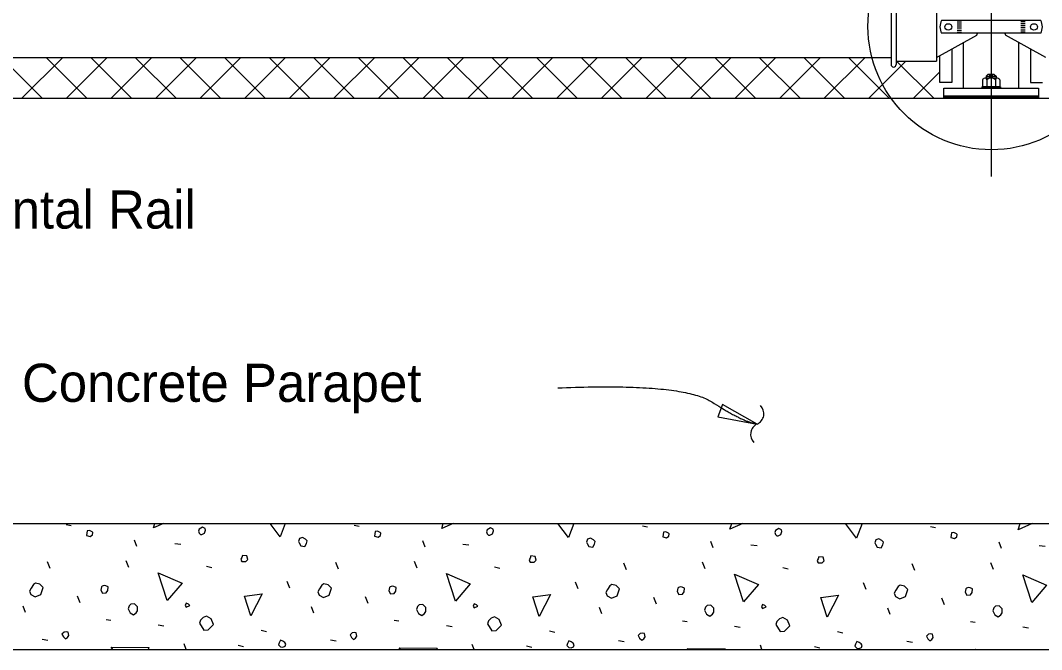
# Model space of a CAD drawing. Extents: x 110698 to 110915, y 110390 to 110472.
# Drawn here: x 110781.01 to 110786.41, y 110452.9 to 110456.22 of the extents above; entities that cross this region are included whole.
import ezdxf

# ---------------------------------------------------------------- set-up
doc = ezdxf.new("R2010")
doc.units = 0
for name, color, linetype in [('AdhocPoint_dp', 7, 'Continuous'), ('Border', 7, 'Continuous'), ('PlotBorder_dp', 7, 'Continuous'), ('SheetBorder_dp', 7, 'Continuous'), ('SheetLines_dp', 7, 'Continuous'), ('TextMisc', 7, 'Continuous')]:
    doc.layers.add(name, color=color, linetype=linetype)

msp = doc.modelspace()

# ---------------------------------------------------------------- linework, layer by layer
at = {"layer": 'AdhocPoint_dp'}
msp.add_line((110786.1408, 110463.3097), (110786.1408, 110455.3996), dxfattribs=at)
at = {"layer": 'PlotBorder_dp'}
msp.add_line((110786.1408, 110455.8731), (110786.1408, 110455.8724), dxfattribs=at)
msp.add_lwpolyline([(110784.9036, 110454.0892), (110784.72, 110454.1937), (110784.6958, 110454.1274)], close=True, dxfattribs=at)
msp.add_circle((110786.1422, 110456.193), 0.6527, dxfattribs=at)
for centre, start, end in [((110784.8793, 110454.1441), 294.1466, 45.8738), ((110784.9281, 110454.0353), 114.1466, 225.8738)]:
    msp.add_arc(centre, 0.0596, start, end, dxfattribs=at)
msp.add_open_spline([(110783.8491, 110454.2807), (110784.5058, 110454.309), (110784.8272, 110454.1009), (110784.9038, 110454.0897)], degree=2, dxfattribs=at)
at = {"layer": 'SheetBorder_dp'}
for p, q in [((110781.1232, 110455.8133), (110780.9097, 110456.0268)), ((110781.2293, 110456.0268), (110781.0157, 110455.8133)), ((110781.3589, 110455.8133), (110781.1454, 110456.0268)), ((110781.465, 110456.0268), (110781.2514, 110455.8133)), ((110781.5946, 110455.8133), (110781.3811, 110456.0268)), ((110781.7007, 110456.0268), (110781.4871, 110455.8133)), ((110781.8303, 110455.8133), (110781.6168, 110456.0268)), ((110781.9364, 110456.0268), (110781.7228, 110455.8133)), ((110782.066, 110455.8133), (110781.8525, 110456.0268)), ((110782.1721, 110456.0268), (110781.9586, 110455.8133)), ((110782.3017, 110455.8133), (110782.0882, 110456.0268)), ((110782.4078, 110456.0268), (110782.1943, 110455.8133)), ((110782.5374, 110455.8133), (110782.3239, 110456.0268)), ((110782.6435, 110456.0268), (110782.43, 110455.8133)), ((110782.7731, 110455.8133), (110782.5596, 110456.0268)), ((110782.8792, 110456.0268), (110782.6657, 110455.8133)), ((110783.0088, 110455.8133), (110782.7953, 110456.0268)), ((110783.1149, 110456.0268), (110782.9014, 110455.8133)), ((110783.2445, 110455.8133), (110783.031, 110456.0268)), ((110783.3506, 110456.0268), (110783.1371, 110455.8133)), ((110783.4802, 110455.8133), (110783.2667, 110456.0268)), ((110783.5863, 110456.0268), (110783.3728, 110455.8133)), ((110783.7159, 110455.8133), (110783.5024, 110456.0268)), ((110783.822, 110456.0268), (110783.6085, 110455.8133)), ((110783.9516, 110455.8133), (110783.7381, 110456.0268)), ((110784.0577, 110456.0268), (110783.8442, 110455.8133)), ((110784.1873, 110455.8133), (110783.9738, 110456.0268)), ((110784.2934, 110456.0268), (110784.0799, 110455.8133)), ((110784.423, 110455.8133), (110784.2095, 110456.0268)), ((110784.5291, 110456.0268), (110784.3156, 110455.8133)), ((110784.6587, 110455.8133), (110784.4452, 110456.0268)), ((110784.7648, 110456.0268), (110784.5513, 110455.8133)), ((110784.8944, 110455.8133), (110784.6809, 110456.0268)), ((110785.0005, 110456.0268), (110784.787, 110455.8133)), ((110785.1301, 110455.8133), (110784.9166, 110456.0268)), ((110785.2362, 110456.0268), (110785.0227, 110455.8133)), ((110785.3658, 110455.8133), (110785.1523, 110456.0268)), ((110785.4719, 110456.0268), (110785.2584, 110455.8133)), ((110785.6015, 110455.8133), (110785.388, 110456.0268)), ((110785.6904, 110456.0096), (110785.4941, 110455.8133)), ((110785.8372, 110455.8133), (110785.6409, 110456.0096)), ((110785.8699, 110455.9534), (110785.7298, 110455.8133)), ((110786.1296, 110455.9348), (110786.1503, 110455.9348)), ((110786.1296, 110455.9251), (110786.1503, 110455.9251)), ((110785.8908, 110455.8202), (110786.3908, 110455.8202)), ((110785.8908, 110455.8167), (110786.3908, 110455.8167)), ((110781.2486, 110453.5577), (110781.2751, 110453.5524)), ((110782.7724, 110453.5542), (110782.799, 110453.5489)), ((110784.2963, 110453.5507), (110784.3228, 110453.5453)), ((110785.8201, 110453.5471), (110785.8466, 110453.5418)), ((110781.6234, 110453.4411), (110781.611, 110453.4746)), ((110781.8232, 110453.457), (110781.855, 110453.4534)), ((110783.1472, 110453.4375), (110783.1348, 110453.4711)), ((110783.347, 110453.4534), (110783.3788, 110453.4499)), ((110784.671, 110453.434), (110784.6586, 110453.4676)), ((110784.8708, 110453.4499), (110784.9026, 110453.4464)), ((110786.1948, 110453.4304), (110786.1825, 110453.464)), ((110786.3946, 110453.4464), (110786.4264, 110453.4428)), ((110781.1655, 110453.3261), (110781.1514, 110453.3615)), ((110781.581, 110453.3314), (110781.5668, 110453.3668)), ((110781.9911, 110453.3385), (110782.0194, 110453.3314)), ((110782.6894, 110453.3226), (110782.6752, 110453.358)), ((110783.1048, 110453.3279), (110783.0906, 110453.3633)), ((110783.5149, 110453.335), (110783.5432, 110453.3279)), ((110784.2132, 110453.3191), (110784.199, 110453.3544)), ((110784.6286, 110453.3244), (110784.6145, 110453.3597)), ((110785.0387, 110453.3314), (110785.067, 110453.3244)), ((110785.737, 110453.3155), (110785.7228, 110453.3509)), ((110786.1524, 110453.3208), (110786.1383, 110453.3562)), ((110782.433, 110453.2218), (110782.4189, 110453.2572)), ((110783.9568, 110453.2183), (110783.9427, 110453.2537)), ((110785.4807, 110453.2148), (110785.4665, 110453.2501)), ((110781.3229, 110453.1441), (110781.3087, 110453.1794)), ((110782.8467, 110453.1405), (110782.8325, 110453.1759)), ((110784.3705, 110453.137), (110784.3564, 110453.1723)), ((110785.8943, 110453.1335), (110785.8802, 110453.1688)), ((110781.0347, 110453.0928), (110781.0224, 110453.1264)), ((110782.5585, 110453.0893), (110782.5462, 110453.1229)), ((110784.0824, 110453.0857), (110784.07, 110453.1193)), ((110785.6062, 110453.0822), (110785.5938, 110453.1158)), ((110781.4608, 110453.0557), (110781.4855, 110453.0521)), ((110782.9846, 110453.0521), (110783.0093, 110453.0486)), ((110781.7365, 110453.0274), (110781.7666, 110453.0221)), ((110782.281, 110452.9991), (110782.3093, 110452.992)), ((110783.2603, 110453.0239), (110783.2904, 110453.0186)), ((110784.5084, 110453.0486), (110784.5331, 110453.0451)), ((110784.7842, 110453.0203), (110784.8142, 110453.015)), ((110786.0322, 110453.0451), (110786.057, 110453.0415)), ((110786.308, 110453.0168), (110786.338, 110453.0115)), ((110781.1231, 110452.9514), (110781.1532, 110452.9461)), ((110782.6469, 110452.9478), (110782.677, 110452.9425)), ((110783.8048, 110452.9956), (110783.8331, 110452.9885)), ((110784.1707, 110452.9443), (110784.2008, 110452.939)), ((110785.3286, 110452.992), (110785.3569, 110452.985)), ((110781.8837, 110452.8966), (110781.8726, 110452.9266)), ((110782.159, 110452.9196), (110782.1873, 110452.9125)), ((110783.4062, 110452.8966), (110783.3965, 110452.9231)), ((110783.6828, 110452.916), (110783.7111, 110452.909)), ((110784.9287, 110452.8966), (110784.9203, 110452.9196)), ((110785.2067, 110452.9125), (110785.2349, 110452.9054)), ((110785.6946, 110452.9408), (110785.7246, 110452.9355))]:
    msp.add_line(p, q, dxfattribs=at)
msp.add_lwpolyline([(110785.8908, 110455.8237), (110786.3908, 110455.8237), (110786.3908, 110455.8133), (110785.8908, 110455.8133)], close=True, dxfattribs=at)
for points in [[(110781.7118, 110453.54), (110781.7189, 110453.5632)], [(110781.7634, 110453.5632), (110781.7118, 110453.54)], [(110781.9593, 110453.5047), (110781.9663, 110453.5047), (110781.9805, 110453.5118), (110781.9858, 110453.5277), (110781.984, 110453.5365), (110781.9699, 110453.5436), (110781.9522, 110453.533), (110781.9487, 110453.5224), (110781.9522, 110453.5118), (110781.9593, 110453.5047)], [(110782.3818, 110453.4923), (110782.3279, 110453.5632)], [(110782.4083, 110453.5632), (110782.3818, 110453.4923)], [(110783.2356, 110453.5365), (110783.2438, 110453.5632)], [(110783.2951, 110453.5632), (110783.2356, 110453.5365)], [(110783.4831, 110453.5012), (110783.4902, 110453.5012), (110783.5043, 110453.5082), (110783.5096, 110453.5241), (110783.5078, 110453.533), (110783.4937, 110453.54), (110783.476, 110453.5294), (110783.4725, 110453.5188), (110783.476, 110453.5082), (110783.4831, 110453.5012)], [(110783.9056, 110453.4888), (110783.849, 110453.5632)], [(110783.9334, 110453.5632), (110783.9056, 110453.4888)], [(110784.7594, 110453.533), (110784.7687, 110453.5632)], [(110784.8268, 110453.5632), (110784.7594, 110453.533)], [(110785.0069, 110453.4976), (110785.014, 110453.4976), (110785.0281, 110453.5047), (110785.0334, 110453.5206), (110785.0316, 110453.5294), (110785.0175, 110453.5365), (110784.9998, 110453.5259), (110784.9963, 110453.5153), (110784.9998, 110453.5047), (110785.0069, 110453.4976)], [(110785.4294, 110453.4852), (110785.3701, 110453.5632)], [(110785.4585, 110453.5632), (110785.4294, 110453.4852)], [(110786.2832, 110453.5294), (110786.2936, 110453.5632)], [(110786.3585, 110453.5632), (110786.2832, 110453.5294)], [(110781.3565, 110453.4994), (110781.3759, 110453.4941), (110781.3883, 110453.5029), (110781.39, 110453.5153), (110781.3865, 110453.5188), (110781.3724, 110453.5259), (110781.36, 110453.5241), (110781.3582, 110453.5118), (110781.3565, 110453.4994)], [(110782.4808, 110453.4605), (110782.4896, 110453.4446), (110782.5108, 110453.4411), (110782.5197, 110453.457), (110782.5232, 110453.4711), (110782.5143, 110453.4799), (110782.4984, 110453.4888), (110782.4825, 110453.4835), (110782.4772, 110453.4676), (110782.4808, 110453.4605)], [(110782.8803, 110453.4959), (110782.8997, 110453.4905), (110782.9121, 110453.4994), (110782.9139, 110453.5118), (110782.9103, 110453.5153), (110782.8962, 110453.5224), (110782.8838, 110453.5206), (110782.882, 110453.5082), (110782.8803, 110453.4959)], [(110784.0046, 110453.457), (110784.0134, 110453.4411), (110784.0346, 110453.4375), (110784.0435, 110453.4534), (110784.047, 110453.4676), (110784.0382, 110453.4764), (110784.0223, 110453.4852), (110784.0063, 110453.4799), (110784.001, 110453.464), (110784.0046, 110453.457)], [(110784.4041, 110453.4923), (110784.4235, 110453.487), (110784.4359, 110453.4959), (110784.4377, 110453.5082), (110784.4341, 110453.5118), (110784.42, 110453.5188), (110784.4076, 110453.5171), (110784.4059, 110453.5047), (110784.4041, 110453.4923)], [(110785.5284, 110453.4534), (110785.5372, 110453.4375), (110785.5584, 110453.434), (110785.5673, 110453.4499), (110785.5708, 110453.464), (110785.562, 110453.4729), (110785.5461, 110453.4817), (110785.5302, 110453.4764), (110785.5249, 110453.4605), (110785.5284, 110453.4534)], [(110785.9279, 110453.4888), (110785.9474, 110453.4835), (110785.9597, 110453.4923), (110785.9615, 110453.5047), (110785.958, 110453.5082), (110785.9438, 110453.5153), (110785.9314, 110453.5135), (110785.9297, 110453.5012), (110785.9279, 110453.4888)], [(110782.1785, 110453.3633), (110782.1997, 110453.3633), (110782.2103, 110453.3739), (110782.205, 110453.3933), (110782.182, 110453.3951), (110782.1785, 110453.3845), (110782.1732, 110453.3756), (110782.1785, 110453.3633), (110782.1749, 110453.3668)], [(110783.7023, 110453.3597), (110783.7235, 110453.3597), (110783.7341, 110453.3703), (110783.7288, 110453.3898), (110783.7058, 110453.3916), (110783.7023, 110453.3809), (110783.697, 110453.3721), (110783.7023, 110453.3597), (110783.6988, 110453.3633)], [(110785.2261, 110453.3562), (110785.2473, 110453.3562), (110785.2579, 110453.3668), (110785.2526, 110453.3862), (110785.2296, 110453.388), (110785.2261, 110453.3774), (110785.2208, 110453.3686), (110785.2261, 110453.3562), (110785.2226, 110453.3597)], [(110781.7843, 110453.1564), (110781.7365, 110453.3032), (110781.862, 110453.2484), (110781.7843, 110453.1564)], [(110783.3081, 110453.1529), (110783.2603, 110453.2996), (110783.3859, 110453.2448), (110783.3081, 110453.1529)], [(110784.8319, 110453.1494), (110784.7842, 110453.2961), (110784.9097, 110453.2413), (110784.8319, 110453.1494)], [(110786.3557, 110453.1458), (110786.308, 110453.2926), (110786.4335, 110453.2378), (110786.3557, 110453.1458)], [(110781.063, 110453.1883), (110781.086, 110453.1759), (110781.116, 110453.1883), (110781.1284, 110453.2254), (110781.1107, 110453.2431), (110781.0878, 110453.2484), (110781.0772, 110453.2413), (110781.0648, 110453.2218), (110781.0559, 110453.2059), (110781.063, 110453.1883)], [(110781.4325, 110453.2112), (110781.4413, 110453.1953), (110781.4608, 110453.1971), (110781.4696, 110453.2095), (110781.4714, 110453.2289), (110781.459, 110453.2342), (110781.4502, 110453.236), (110781.4395, 110453.2325), (110781.436, 110453.2289), (110781.4325, 110453.2112)], [(110782.5868, 110453.1847), (110782.6098, 110453.1723), (110782.6399, 110453.1847), (110782.6522, 110453.2218), (110782.6346, 110453.2395), (110782.6116, 110453.2448), (110782.601, 110453.2378), (110782.5886, 110453.2183), (110782.5798, 110453.2024), (110782.5868, 110453.1847)], [(110782.9563, 110453.2077), (110782.9651, 110453.1918), (110782.9846, 110453.1936), (110782.9934, 110453.2059), (110782.9952, 110453.2254), (110782.9828, 110453.2307), (110782.974, 110453.2325), (110782.9634, 110453.2289), (110782.9598, 110453.2254), (110782.9563, 110453.2077)], [(110784.1106, 110453.1812), (110784.1336, 110453.1688), (110784.1637, 110453.1812), (110784.176, 110453.2183), (110784.1584, 110453.236), (110784.1354, 110453.2413), (110784.1248, 110453.2342), (110784.1124, 110453.2148), (110784.1036, 110453.1989), (110784.1106, 110453.1812)], [(110784.4801, 110453.2042), (110784.4889, 110453.1883), (110784.5084, 110453.19), (110784.5172, 110453.2024), (110784.519, 110453.2218), (110784.5066, 110453.2272), (110784.4978, 110453.2289), (110784.4872, 110453.2254), (110784.4836, 110453.2218), (110784.4801, 110453.2042)], [(110785.6345, 110453.1777), (110785.6574, 110453.1653), (110785.6875, 110453.1777), (110785.6999, 110453.2148), (110785.6822, 110453.2325), (110785.6592, 110453.2378), (110785.6486, 110453.2307), (110785.6362, 110453.2112), (110785.6274, 110453.1953), (110785.6345, 110453.1777)], [(110786.0039, 110453.2006), (110786.0128, 110453.1847), (110786.0322, 110453.1865), (110786.041, 110453.1989), (110786.0428, 110453.2183), (110786.0304, 110453.2236), (110786.0216, 110453.2254), (110786.011, 110453.2218), (110786.0075, 110453.2183), (110786.0039, 110453.2006)], [(110782.2262, 110453.0751), (110782.1926, 110453.1794), (110782.2863, 110453.1918), (110782.2262, 110453.0751)], [(110783.75, 110453.0716), (110783.7164, 110453.1759), (110783.8101, 110453.1883), (110783.75, 110453.0716)], [(110785.2738, 110453.0681), (110785.2402, 110453.1723), (110785.3339, 110453.1847), (110785.2738, 110453.0681)], [(110781.5774, 110453.1122), (110781.588, 110453.091), (110781.6057, 110453.0804), (110781.6199, 110453.091), (110781.6269, 110453.1016), (110781.6269, 110453.1229), (110781.611, 110453.1388), (110781.5916, 110453.137), (110781.5827, 110453.1282), (110781.5774, 110453.1122)], [(110781.8833, 110453.1211), (110781.9027, 110453.1299), (110781.8956, 110453.137), (110781.8833, 110453.1423), (110781.878, 110453.1299), (110781.8833, 110453.1211)], [(110783.1012, 110453.1087), (110783.1119, 110453.0875), (110783.1295, 110453.0769), (110783.1437, 110453.0875), (110783.1507, 110453.0981), (110783.1507, 110453.1193), (110783.1348, 110453.1352), (110783.1154, 110453.1335), (110783.1065, 110453.1246), (110783.1012, 110453.1087)], [(110783.4071, 110453.1175), (110783.4265, 110453.1264), (110783.4194, 110453.1335), (110783.4071, 110453.1388), (110783.4018, 110453.1264), (110783.4071, 110453.1175)], [(110784.6251, 110453.1052), (110784.6357, 110453.084), (110784.6533, 110453.0734), (110784.6675, 110453.084), (110784.6746, 110453.0946), (110784.6746, 110453.1158), (110784.6586, 110453.1317), (110784.6392, 110453.1299), (110784.6304, 110453.1211), (110784.6251, 110453.1052)], [(110784.9309, 110453.114), (110784.9503, 110453.1229), (110784.9433, 110453.1299), (110784.9309, 110453.1352), (110784.9256, 110453.1229), (110784.9309, 110453.114)], [(110786.1489, 110453.1016), (110786.1595, 110453.0804), (110786.1772, 110453.0698), (110786.1913, 110453.0804), (110786.1984, 110453.091), (110786.1984, 110453.1122), (110786.1825, 110453.1282), (110786.163, 110453.1264), (110786.1542, 110453.1175), (110786.1489, 110453.1016)], [(110781.954, 110453.0362), (110781.9769, 110452.9991), (110781.9999, 110453.0009), (110782.0088, 110453.0097), (110782.0282, 110453.0292), (110782.0158, 110453.0592), (110781.9911, 110453.0734), (110781.9734, 110453.0663), (110781.9593, 110453.0521), (110781.954, 110453.0362)], [(110783.4778, 110453.0327), (110783.5008, 110452.9956), (110783.5237, 110452.9973), (110783.5326, 110453.0062), (110783.552, 110453.0256), (110783.5397, 110453.0557), (110783.5149, 110453.0698), (110783.4972, 110453.0627), (110783.4831, 110453.0486), (110783.4778, 110453.0327)], [(110785.0016, 110453.0292), (110785.0246, 110452.992), (110785.0476, 110452.9938), (110785.0564, 110453.0026), (110785.0758, 110453.0221), (110785.0635, 110453.0521), (110785.0387, 110453.0663), (110785.021, 110453.0592), (110785.0069, 110453.0451), (110785.0016, 110453.0292)], [(110781.2345, 110452.9638), (110781.2451, 110452.9531), (110781.2557, 110452.9602), (110781.2628, 110452.9708), (110781.2592, 110452.9885), (110781.2504, 110452.9903), (110781.238, 110452.9885), (110781.2274, 110452.9779), (110781.2345, 110452.9638)], [(110782.3835, 110452.9107), (110782.3959, 110452.909), (110782.4083, 110452.9143), (110782.4118, 110452.9249), (110782.4065, 110452.9337), (110782.3959, 110452.9408), (110782.3835, 110452.9461), (110782.3765, 110452.9319), (110782.3729, 110452.9213), (110782.3835, 110452.9107)], [(110782.7583, 110452.9602), (110782.7689, 110452.9496), (110782.7795, 110452.9567), (110782.7866, 110452.9673), (110782.783, 110452.985), (110782.7742, 110452.9867), (110782.7618, 110452.985), (110782.7512, 110452.9744), (110782.7583, 110452.9602)], [(110783.9073, 110452.9072), (110783.9197, 110452.9054), (110783.9321, 110452.9107), (110783.9356, 110452.9213), (110783.9303, 110452.9302), (110783.9197, 110452.9372), (110783.9073, 110452.9425), (110783.9003, 110452.9284), (110783.8967, 110452.9178), (110783.9073, 110452.9072)], [(110784.2821, 110452.9567), (110784.2927, 110452.9461), (110784.3033, 110452.9531), (110784.3104, 110452.9638), (110784.3069, 110452.9814), (110784.298, 110452.9832), (110784.2856, 110452.9814), (110784.275, 110452.9708), (110784.2821, 110452.9567)], [(110785.8059, 110452.9531), (110785.8165, 110452.9425), (110785.8271, 110452.9496), (110785.8342, 110452.9602), (110785.8307, 110452.9779), (110785.8218, 110452.9797), (110785.8095, 110452.9779), (110785.7989, 110452.9673), (110785.8059, 110452.9531)], [(110781.4967, 110452.8966), (110781.4873, 110452.909), (110781.687, 110452.9072), (110781.6831, 110452.8966)], [(110783.0178, 110452.8966), (110783.0111, 110452.9054), (110783.2108, 110452.9036), (110783.2082, 110452.8966)], [(110784.5389, 110452.8966), (110784.5349, 110452.9019), (110784.7347, 110452.9001), (110784.7333, 110452.8966)], [(110785.4312, 110452.9036), (110785.4435, 110452.9019), (110785.4559, 110452.9072), (110785.4594, 110452.9178), (110785.4541, 110452.9266), (110785.4435, 110452.9337), (110785.4312, 110452.939), (110785.4241, 110452.9249), (110785.4206, 110452.9143), (110785.4312, 110452.9036)], [(110786.0601, 110452.8966), (110786.0587, 110452.8983), (110786.2585, 110452.8966)]]:
    msp.add_lwpolyline(points, dxfattribs=at)
at = {"layer": 'SheetLines_dp'}
for p, q in [((110779.5973, 110455.8133), (110792.755, 110455.8133)), ((110774.7539, 110453.5632), (110797.5277, 110453.5632)), ((110774.7539, 110452.8966), (110797.5277, 110452.8966))]:
    msp.add_line(p, q, dxfattribs=at)
at = {"layer": 'TextMisc'}
for p, q in [((110785.6114, 110456.3014), (110785.6114, 110455.9917)), ((110785.6383, 110456.3014), (110785.6383, 110455.9917)), ((110785.8512, 110456.2818), (110785.8512, 110456.0096)), ((110786.4031, 110456.2245), (110785.8784, 110456.2245)), ((110785.9608, 110456.2167), (110785.9842, 110456.2167)), ((110785.9608, 110456.2071), (110785.9842, 110456.2071)), ((110785.9608, 110456.1963), (110785.9842, 110456.1963)), ((110785.9608, 110456.1845), (110785.9842, 110456.1845)), ((110786.3208, 110456.2167), (110786.2973, 110456.2167)), ((110786.3208, 110456.2071), (110786.2973, 110456.2071)), ((110786.3208, 110456.1963), (110786.2973, 110456.1963)), ((110786.3208, 110456.1845), (110786.2973, 110456.1845)), ((110785.8512, 110456.0277), (110786.0652, 110456.1463)), ((110786.4031, 110456.1567), (110785.8784, 110456.1567)), ((110785.9608, 110456.1727), (110785.9842, 110456.1727)), ((110785.9608, 110456.1629), (110785.9842, 110456.1629)), ((110786.4303, 110456.0277), (110786.2164, 110456.1463)), ((110786.3208, 110456.1727), (110786.2973, 110456.1727)), ((110786.3208, 110456.1629), (110786.2973, 110456.1629)), ((110785.995, 110455.8653), (110785.995, 110456.1073)), ((110786.2866, 110455.8653), (110786.2866, 110456.1073)), ((110785.6114, 110456.0268), (110776.6701, 110456.0268)), ((110785.8699, 110455.8966), (110785.8699, 110456.038)), ((110785.9324, 110456.0727), (110785.9324, 110455.8966)), ((110786.3491, 110456.0727), (110786.3491, 110455.8966)), ((110785.6383, 110456.0096), (110785.8512, 110456.0096)), ((110786.1748, 110455.9187), (110786.1067, 110455.9187)), ((110786.1247, 110455.9397), (110786.115, 110455.93)), ((110786.115, 110455.93), (110786.115, 110455.9187)), ((110786.115, 110455.93), (110786.1665, 110455.93)), ((110786.1247, 110455.9397), (110786.1552, 110455.9397)), ((110786.1552, 110455.9397), (110786.1665, 110455.93)), ((110786.1665, 110455.93), (110786.1665, 110455.9187)), ((110785.9324, 110455.8966), (110785.8699, 110455.8966)), ((110786.0911, 110455.8724), (110786.0911, 110455.8653)), ((110786.0911, 110455.8724), (110786.1905, 110455.8724)), ((110786.0953, 110455.9101), (110786.0953, 110455.8724)), ((110786.1861, 110455.8724), (110786.0953, 110455.8724)), ((110786.118, 110455.9103), (110786.118, 110455.8724)), ((110786.1634, 110455.9103), (110786.1634, 110455.8724)), ((110786.1861, 110455.9101), (110786.1861, 110455.8724)), ((110786.1905, 110455.8724), (110786.1905, 110455.8653)), ((110786.3491, 110455.8966), (110786.4116, 110455.8966)), ((110786.021, 110455.8237), (110786.2606, 110455.8237))]:
    msp.add_line(p, q, dxfattribs=at)
msp.add_lwpolyline([(110785.8908, 110455.8653), (110786.3908, 110455.8653), (110786.3908, 110455.8237), (110785.8908, 110455.8237)], close=True, dxfattribs=at)
for centre, radius, start, end in [((110785.6249, 110455.9915), 0.0134, 180, 0), ((110786.1068, 110455.907), 0.0118, 16.5986, 164.7005), ((110786.1408, 110455.884), 0.0347, 49.2015, 130.7985), ((110786.1748, 110455.907), 0.0118, 15.1506, 163.5042)]:
    msp.add_arc(centre, radius, start, end, dxfattribs=at)
for centre, major_axis, start_param, end_param in [((110785.9475, 110456.1905), (-0.0776, 0), 5.810211, 6.75616), ((110786.334, 110456.1905), (0.0776, 0), 5.810211, 6.75616), ((110785.9276, 110456.1925), (0.146, 0), 5.947976, 6.024627), ((110786.354, 110456.1925), (-0.146, 0), 0.258558, 0.335209)]:
    msp.add_ellipse(centre, major_axis=major_axis, ratio=0.957868, start_param=start_param, end_param=end_param, dxfattribs=at)
for centre, major_axis in [((110785.9142, 110456.19), (0.0178, 0)), ((110786.3673, 110456.19), (-0.0178, 0))]:
    msp.add_ellipse(centre, major_axis=major_axis, ratio=0.957868, dxfattribs=at)

# ---------------------------------------------------------------- texts
at = {"layer": 'Border'}
for s, p in [('Horizontal Rail', (110780.1822, 110455.1236)), ('Concrete Parapet', (110781.0155, 110454.207))]:
    msp.add_text(s, height=0.2016, dxfattribs=at).set_placement(p)

doc.saveas('drawing.dxf')
